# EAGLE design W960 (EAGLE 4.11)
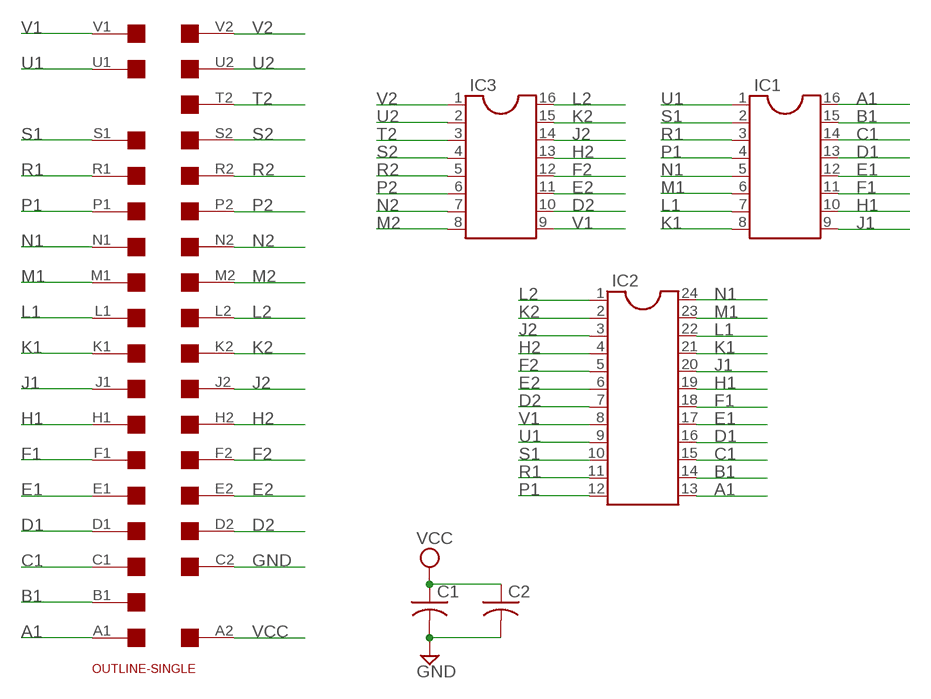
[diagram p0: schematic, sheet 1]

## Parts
C1  C-US050-025X075  [C050-025X075]
C2  C-US050-025X075  [C050-025X075]
IC1  DIL16  [DIL16]
IC2  DIL24-6  [DIL24-6]
IC3  DIL16  [DIL16]
U$1  EDGE-2CONNECTOR  [EDGE-CON2]
U$2  OUTLINE-SINGLE  [SINGLE]

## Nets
A1: IC1.16 IC2.13 U$1.A1
B1: IC1.15 IC2.14 U$1.B1
C1: IC1.14 IC2.15 U$1.C1
D1: IC1.13 IC2.16 U$1.D1
D2: IC2.7 IC3.10 U$1.D2
E1: IC1.12 IC2.17 U$1.E1
E2: IC2.6 IC3.11 U$1.E2
F1: IC1.11 IC2.18 U$1.F1
F2: IC2.5 IC3.12 U$1.F2
GND: C1.2 C2.2 U$1.C2
H1: IC1.10 IC2.19 U$1.H1
H2: IC2.4 IC3.13 U$1.H2
J1: IC1.9 IC2.20 U$1.J1
J2: IC2.3 IC3.14 U$1.J2
K1: IC1.8 IC2.21 U$1.K1
K2: IC2.2 IC3.15 U$1.K2
L1: IC1.7 IC2.22 U$1.L1
L2: IC2.1 IC3.16 U$1.L2
M1: IC1.6 IC2.23 U$1.M1
M2: IC3.8 U$1.M2
N1: IC1.5 IC2.24 U$1.N1
N2: IC3.7 U$1.N2
P1: IC1.4 IC2.12 U$1.P1
P2: IC3.6 U$1.P2
R1: IC1.3 IC2.11 U$1.R1
R2: IC3.5 U$1.R2
S1: IC1.2 IC2.10 U$1.S1
S2: IC3.4 U$1.S2
T2: IC3.3 U$1.T2
U1: IC1.1 IC2.9 U$1.U1
U2: IC3.2 U$1.U2
V1: IC2.8 IC3.9 U$1.V1
V2: IC3.1 U$1.V2
VCC: C1.1 C2.1 U$1.A2
Unconnected: U$1.B2 U$1.T1

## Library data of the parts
C1 C2 = rcl:C-US: CAPACITOR, American symbol
IC1 IC3 = ic-package:DIL16: Dual In Line
IC2 = ic-package:DIL24: Dual In Line
U$1 = dec-con:EDGE-2: Double-Sided DEC edge connector.
U$2 = dec-con:OUTLINE-*: Board outlines for DEC boards.

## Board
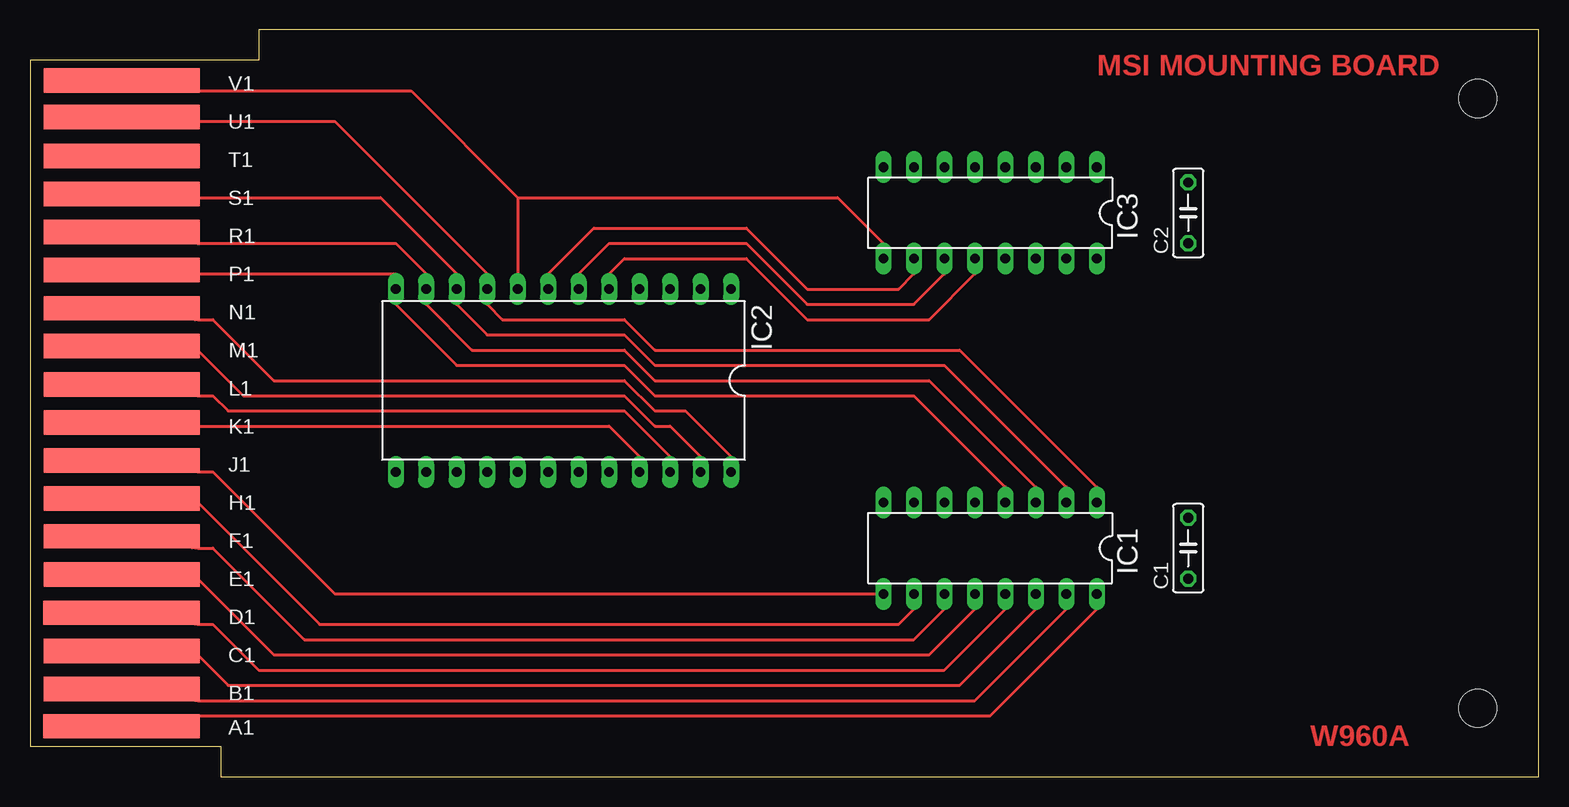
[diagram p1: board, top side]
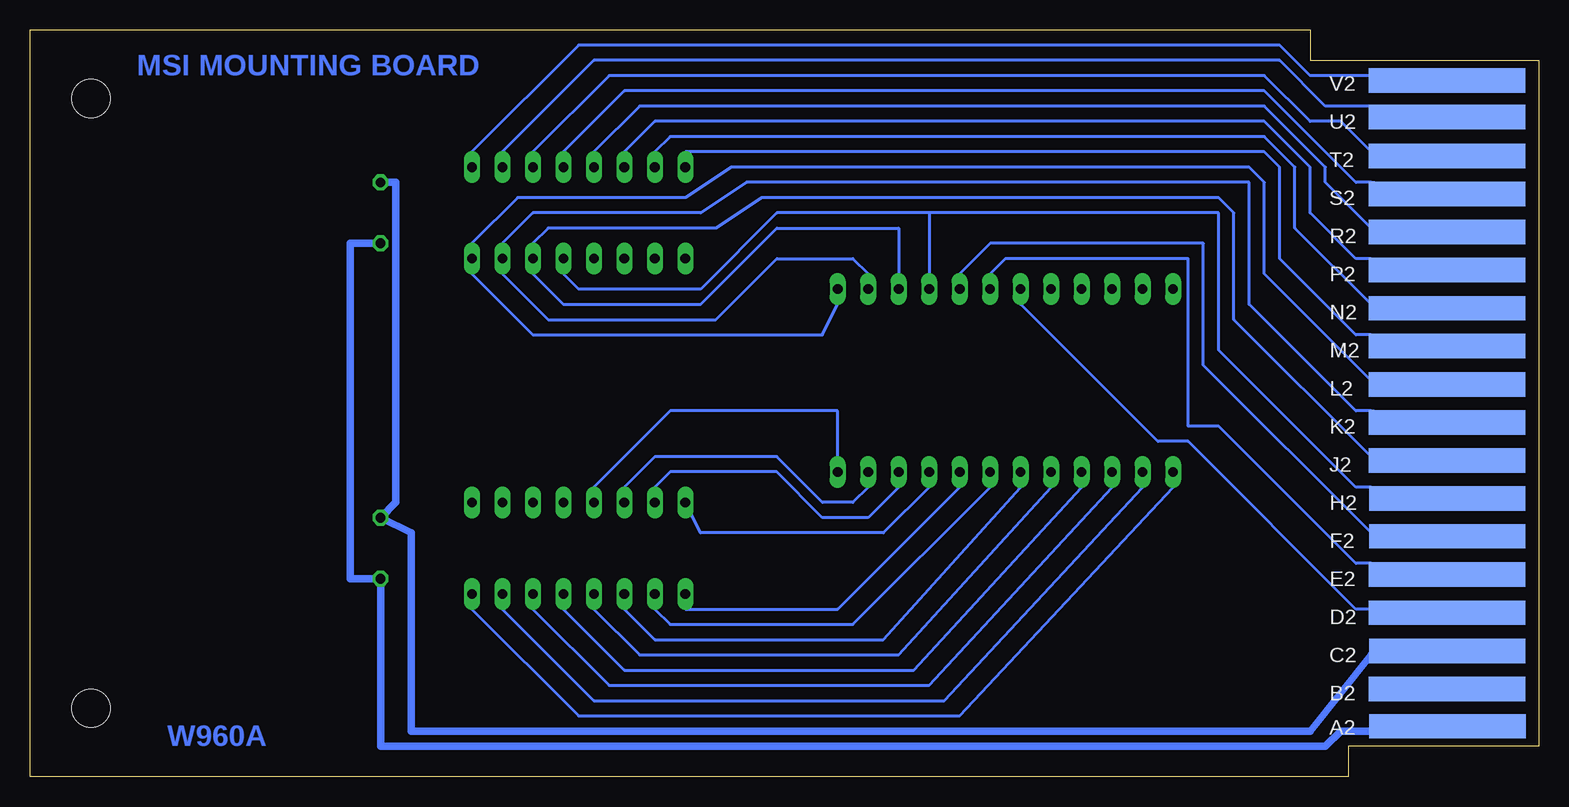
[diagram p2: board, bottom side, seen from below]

Size 125.73 x 62.23 mm. Coordinates in mm from the lower left corner, seen from the top.
Copper layers (1*16): Top 0.035mm / dielectric 1.5mm / Bottom 0.035mm
Design rules "10mils": minimum track width 10mil, minimum drill 24mil, track to track 10mil, track to pad 10mil, pad to pad 10mil, via to via 10mil, smd to smd 10mil, copper to edge 25mil, drill to drill 10mil, minimum pad ring 10mil, minimum via ring 8mil, stop-mask expansion 0mil, vias tented up to drill 0mil, thermal gap 10mil

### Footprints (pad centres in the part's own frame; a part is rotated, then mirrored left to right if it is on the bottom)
C050-025X075 = drill 0.813 octagon: 1 -2.54,0; 2 2.54,0
DIL16 = drill 0.813 long: 1 -8.89,-3.81; 2 -6.35,-3.81; 3 -3.81,-3.81; 4 -1.27,-3.81; 5 1.27,-3.81; 6 3.81,-3.81; 7 6.35,-3.81; 8 8.89,-3.81; 9 8.89,3.81; 10 6.35,3.81; 11 3.81,3.81; 12 1.27,3.81; 13 -1.27,3.81; 14 -3.81,3.81; 15 -6.35,3.81; 16 -8.89,3.81
DIL24-6 = drill 0.813 long: 1 -13.97,-7.62; 2 -11.43,-7.62; 3 -8.89,-7.62; 4 -6.35,-7.62; 5 -3.81,-7.62; 6 -1.27,-7.62; 7 1.27,-7.62; 8 3.81,-7.62; 9 6.35,-7.62; 10 8.89,-7.62; 11 11.43,-7.62; 12 13.97,-7.62; 13 13.97,7.62; 14 11.43,7.62; 15 8.89,7.62; 16 6.35,7.62; 17 3.81,7.62; 18 1.27,7.62; 19 -1.27,7.62; 20 -3.81,7.62; 21 -6.35,7.62; 22 -8.89,7.62; 23 -11.43,7.62; 24 -13.97,7.62
EDGE-CON2 = smd 13.017 x 2.032: A1 7.633,4.207; B1 7.639,7.327; C1 7.636,10.489; D1 7.633,13.665; E1 7.642,16.84; F1 7.642,20.041; H1 7.642,23.19; J1 7.642,26.34; K1 7.642,29.515; L1 7.642,32.69; M1 7.642,35.89; N1 7.642,39.04; P1 7.642,42.24; R1 7.642,45.39; S1 7.642,48.565; T1 7.642,51.74; U1 7.642,54.966; V1 7.642,58.026 | smd 13.017 x 2.032 bottom: A2 7.614,4.207; B2 7.642,7.328; C2 7.617,10.49; D2 7.642,13.665; E2 7.642,16.84; F2 7.617,20.041; H2 7.617,23.19; J2 7.642,26.34; K2 7.642,29.515; L2 7.642,32.69; M2 7.642,35.89; N2 7.642,39.04; P2 7.642,42.24; R2 7.642,45.39; S2 7.642,48.565; T2 7.642,51.74; U2 7.642,54.966; V2 7.642,58.026
SINGLE = hole 3.175: 120.65,56.515; 120.65,5.715

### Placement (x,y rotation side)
C1  96.52,19.05 90 top
C2  96.52,46.99 90 top
IC1  80.01,19.05 180 top
IC2  44.45,33.02 180 top
IC3  80.01,46.99 180 top
U$1  0,0 0 top
U$2  0,0 0 top

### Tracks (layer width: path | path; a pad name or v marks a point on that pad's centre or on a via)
A1
  Top 0.254: IC1.16 88.9,13.97 80.01,5.08 13.97,5.08 U$1.A1
  Bottom 0.254: IC2.13 30.48,24.13 48.26,5.08 80.01,5.08 88.9,13.97 IC1.16
B1
  Top 0.254: IC1.15 86.36,13.97 78.74,6.35 13.97,6.35 U$1.B1
  Bottom 0.254: IC2.14 33.02,24.13 49.53,6.35 78.74,6.35 86.36,13.97 IC1.15
C1
  Top 0.254: IC1.14 83.82,13.97 77.47,7.62 16.51,7.62 13.97,10.16 U$1.C1
  Bottom 0.254: IC2.15 35.56,24.13 50.8,7.62 77.47,7.62 83.82,13.97 IC1.14
D1
  Top 0.254: IC1.13 81.28,13.97 76.2,8.89 19.05,8.89 15.24,12.7 13.97,12.7 U$1.D1
  Bottom 0.254: IC2.16 38.1,24.13 52.07,8.89 76.2,8.89 81.28,13.97 IC1.13
D2
  Top 0.254: IC3.10 73.66,41.91 72.39,40.64 64.77,40.64 59.69,45.72 46.99,45.72 43.18,41.91 IC2.7
  Bottom 0.254: IC2.7 43.18,39.37 31.75,27.94 29.21,27.94 15.24,13.97 13.97,13.97 U$1.D2
E1
  Top 0.254: IC1.12 78.74,13.97 74.93,10.16 20.32,10.16 13.97,16.51 U$1.E1
  Bottom 0.254: IC1.12 78.74,13.97 74.93,10.16 53.34,10.16 40.64,24.13 IC2.17
E2
  Top 0.254: IC3.11 76.2,41.91 73.66,39.37 64.77,39.37 59.69,44.45 48.26,44.45 45.72,41.91 IC2.6
  Bottom 0.254: IC2.6 45.72,41.91 44.45,43.18 29.21,43.18 29.21,29.21 26.67,29.21 15.24,17.78 13.97,17.78 U$1.E2
F1
  Top 0.254: IC1.11 76.2,13.97 73.66,11.43 22.86,11.43 15.24,19.05 13.97,19.05 U$1.F1
  Bottom 0.254: IC2.18 43.18,24.13 54.61,11.43 73.66,11.43 76.2,13.97 IC1.11
F2
  Top 0.254: IC2.5 48.26,41.91 49.53,43.18 59.69,43.18 64.77,38.1 74.93,38.1 78.74,41.91 IC3.12
  Bottom 0.254: IC2.5 48.26,41.91 45.72,44.45 27.94,44.45 27.94,34.29 13.97,20.32 U$1.F2
GND
  Bottom 0.254: U$1.C2 13.97,10.16
  Bottom 0.61: C2.2 95.25,49.53 95.25,22.86 C1.2 93.98,20.32 93.98,3.81 19.05,3.81 13.97,10.16
H1
  Top 0.254: IC1.10 73.66,13.97 72.39,12.7 24.13,12.7 13.97,22.86 U$1.H1
  Bottom 0.254: IC1.10 73.66,13.97 72.39,12.7 57.15,12.7 45.72,24.13 IC2.19
H2
  Bottom 0.254: 50.8,46.99 63.5,46.99 69.85,40.64 80.01,40.64 81.28,41.91 IC3.13 | 50.8,46.99 IC2.4 | 50.8,46.99 26.67,46.99 26.67,35.56 15.24,24.13 13.97,24.13 U$1.H2
J1
  Top 0.254: IC1.9 25.4,15.24 15.24,25.4 13.97,25.4 U$1.J1
  Bottom 0.254: IC2.20 48.26,24.13 58.42,13.97 71.12,13.97 IC1.9
J2
  Bottom 0.254: IC2.3 53.34,45.72 63.5,45.72 69.85,39.37 81.28,39.37 83.82,41.91 IC3.14 83.82,44.45 82.55,45.72 68.58,45.72 64.77,48.26 26.67,48.26 25.4,46.99 25.4,38.1 13.97,26.67 U$1.J2
K1
  Top 0.254: IC2.21 50.8,26.67 48.26,29.21 13.97,29.21 U$1.K1
  Bottom 0.254: IC1.8 69.85,20.32 54.61,20.32 50.8,24.13 IC2.21
K2
  Bottom 0.254: IC2.2 55.88,41.91 57.15,43.18 63.5,43.18 68.58,38.1 82.55,38.1 86.36,41.91 IC3.15 86.36,44.45 83.82,46.99 69.85,46.99 66.04,49.53 24.13,49.53 24.13,39.37 15.24,30.48 13.97,30.48 U$1.K2
L1
  Top 0.254: IC2.22 53.34,26.67 49.53,30.48 16.51,30.48 15.24,31.75 13.97,31.75 U$1.L1
  Bottom 0.254: IC1.7 73.66,24.13 72.39,25.4 63.5,25.4 59.69,21.59 55.88,21.59 53.34,24.13 IC2.22
L2
  Bottom 0.254: IC2.1 58.42,39.37 59.69,36.83 83.82,36.83 88.9,41.91 IC3.16 88.9,44.45 85.09,48.26 71.12,48.26 67.31,50.8 24.13,50.8 22.86,49.53 22.86,41.91 13.97,33.02 U$1.L2
M1
  Top 0.254: IC2.23 55.88,26.67 53.34,29.21 52.07,29.21 49.53,31.75 17.78,31.75 13.97,35.56 U$1.M1
  Bottom 0.254: IC1.6 76.2,24.13 73.66,26.67 63.5,26.67 59.69,22.86 57.15,22.86 55.88,24.13 IC2.23
M2
  Bottom 0.254: IC3.8 71.12,52.07 22.86,52.07 21.59,50.8 21.59,43.18 15.24,36.83 13.97,36.83 U$1.M2
N1
  Top 0.254: IC2.24 58.42,26.67 54.61,30.48 52.07,30.48 49.53,33.02 20.32,33.02 15.24,38.1 13.97,38.1 U$1.N1
  Bottom 0.254: IC1.5 78.74,24.13 72.39,30.48 58.42,30.48 IC2.24
N2
  Bottom 0.254: IC3.7 73.66,52.07 72.39,53.34 22.86,53.34 20.32,50.8 20.32,45.72 13.97,39.37 U$1.N2
P1
  Top 0.254: U$1.P1 13.97,41.91 30.48,41.91 IC2.12 30.48,39.37 35.56,34.29 49.53,34.29 52.07,31.75 73.66,31.75 81.28,24.13 IC1.4
P2
  Bottom 0.254: IC3.6 76.2,52.07 73.66,54.61 22.86,54.61 19.05,50.8 19.05,46.99 15.24,43.18 13.97,43.18 U$1.P2
R1
  Top 0.254: U$1.R1 13.97,44.45 30.48,44.45 33.02,41.91 IC2.11 33.02,39.37 36.83,35.56 49.53,35.56 52.07,33.02 74.93,33.02 83.82,24.13 IC1.3
R2
  Bottom 0.254: IC3.5 78.74,52.07 74.93,55.88 22.86,55.88 17.78,50.8 17.78,49.53 13.97,45.72 U$1.R2
S1
  Top 0.254: U$1.S1 13.97,48.26 29.21,48.26 35.56,41.91 IC2.10 35.56,39.37 38.1,36.83 49.53,36.83 52.07,34.29 76.2,34.29 86.36,24.13 IC1.2
S2
  Bottom 0.254: IC3.4 81.28,52.07 76.2,57.15 22.86,57.15 15.24,49.53 13.97,49.53 U$1.S2
T2
  Bottom 0.254: IC3.3 83.82,52.07 77.47,58.42 22.86,58.42 19.05,54.61 16.51,54.61 13.97,52.07 U$1.T2
U1
  Top 0.254: U$1.U1 13.97,54.61 25.4,54.61 38.1,41.91 IC2.9 38.1,39.37 39.37,38.1 49.53,38.1 52.07,35.56 77.47,35.56 88.9,24.13 IC1.1
U2
  Bottom 0.254: IC3.2 86.36,52.07 78.74,59.69 21.59,59.69 17.78,55.88 13.97,55.88 U$1.U2
V1
  Top 0.254: 40.64,48.26 67.31,48.26 71.12,44.45 IC3.9 | U$1.V1 13.97,57.15 31.75,57.15 40.64,48.26 | 40.64,48.26 IC2.8
V2
  Bottom 0.254: IC3.1 88.9,52.07 80.01,60.96 21.59,60.96 19.05,58.42 13.97,58.42 U$1.V2
VCC
  Bottom 0.254: 13.97,5.08 U$1.A2 13.97,3.81
  Bottom 0.61: C2.1 99.06,44.45 99.06,16.51 C1.1 96.52,2.54 17.78,2.54 16.51,3.81 13.97,3.81

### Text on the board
Top: MSI MOUNTING BOARD | W960A
Bottom: MSI MOUNTING BOARD | W960A
tValues: M2 | N2 | P2 | R2 | S2 | T2 | U2 | V2 | P1 | R1 | S1 | U1 | V1 | D2 | E2 | F2 | H2 | J2 | K2 | L2 | V1 | D2 | E2 | F2 | H2 | J2 | K2 | L2 | K1 | L1 | M1 | N1 | P1 | R1 | S1 | U1 | A1 | B1 | C1 | D1 | E1 | F1 | H1 | J1 | K1 | L1 | M1 | N1 | J1 | H1 | F1 | E1 | D1 | C1 | B1 | A1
